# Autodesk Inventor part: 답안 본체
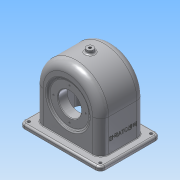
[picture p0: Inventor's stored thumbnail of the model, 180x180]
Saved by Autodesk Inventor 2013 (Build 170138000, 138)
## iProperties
Created: 2016-01
Part Number: 답안 본체
Material: 알루미늄 6061
Document SubType Name: Modeling
Designer: Administrator
Density: 2.71 g/cm^3
Mass: 809.783 g
Surface Area: 999.26 cm^2
Volume: 298.813 cm^3
Author: Administrator
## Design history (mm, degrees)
sketch "스케치1"
  geometry: L1 (-62, 52)-(62, 52); L2 (70, 44)-(70, -44); L3 (62, -52)-(-62, -52); L4 (-70, -44)-(-70, 44); A1 r 8 centre (-62, 44) between (-62, 52) and (-70, 44); A2 r 8 centre (-62, -44) between (-70, -44) and (-62, -52); A3 r 8 centre (62, -44) between (62, -52) and (70, -44); A4 r 8 centre (62, 44) between (70, 44) and (62, 52); 6 further points
  constraints: 8 end point, 8 point on circle, 8 tangent, 6 point on line, 4 centre point, 3 equal radius, 2 midpoint, 2 parallel, 1 horizontal, 1 horizontal alignment, 1 perpendicular, 1 vertical alignment
  dimensions: "d0" = 140 distance of point (-70, 52) point (70, 52); "d2" = 104 distance of point (70, 52) point (70, -52); "d3" = 8 radius of A1
extrude "돌출1" new body sketch "스케치1" distance "d4" = 7; taper "d5" = 0 deg
sketch "스케치2"
  geometry: L1 (62, 7)-(-62, 7) reference; L2 (-57, 7)-(-57, 64); L3 (57, 7)-(57, 64); L4 (-70, 0)-(-70, 7) reference; L5 (-62, 0)-(62, 0) reference; A1 r 57 centre (0, 64) between (57, 64) and (-57, 64); 2 further points
  constraints: 4 end point, 3 point on circle, 2 point on line, 1 centre point, 1 horizontal alignment, 1 parallel, 1 perpendicular, 1 tangent, 1 vertical alignment
  dimensions: "d10" = 57 radius of A1; "d11" = 64 distance from line of L5 L2.end
extrude "돌출2" join sketch "스케치2" stored distance "d12" = 77; taper "d13" = 0 deg
sketch "스케치3"
  geometry: L1 (62, 0)-(-62, 0) reference; C1 r 31 at (0, -60); 1 further point
  constraints: 1 centre point, 1 vertical alignment
  dimensions: "d14" = 62 diameter of C1; "d16" = 60 distance from line of L1 C1.centre
extrude "돌출3" join sketch "스케치3" distance "d17" = 10; taper "d18" = 0 deg
node "작업 평면2"
  node "작업 평면1"
sketch "스케치5"
  geometry: C1 r 6 at (0, 0); 1 further point
  constraints: 1 centre point, 1 coincident
  dimensions: "d20" = 12 diameter of C1
extrude "돌출4" join sketch "스케치5" stored distance "d22" = 5; taper "d23" = 0 deg
sketch "스케치6"
  geometry: L1 (-60.75, 28.203)-(-60.75, 48.797); L2 (-60.75, 48.797)-(14.75, 48.797); L3 (14.75, 48.797)-(14.75, 28.203); L4 (14.75, 28.203)-(-60.75, 28.203); L5 (7, 82.5)-(7, -5.5) reference; 5 further points
  constraints: 3 midpoint, 2 horizontal alignment, 1 parallel, 1 vertical alignment, 2 other
  dimensions: "d24" = 30 distance from line of L5 point (-23, 38.5); "d25" = 7.74973 distance between parallel lines of L3 L5; "d26" = 20.59353 distance between parallel lines of L4 L2
feature "엠보싱1" sketch "스케치6" dims "d0" = 140, "d2" = 104, "d3" = 8, "d27" = 0.5, "d28" = 0
sketch "스케치8"
  geometry: L1 (-57, 7)-(-57, 64) reference; L2 (57, 64)-(57, 7) reference; L3 (-51, 0)-(-51, 64); L4 (51, 64)-(51, 0); L5 (-62, 0)-(62, 0) reference; L6 (-51, 0)-(51, 0); A1 r 57 centre (0, 64) between (57, 64) and (-57, 64) reference; A2 r 51 centre (0, 64) between (51, 64) and (-51, 64); 1 further point
  constraints: 6 end point, 2 horizontal alignment, 2 point on circle, 2 point on line, 2 tangent, 1 centre point
  dimensions: "d30" = 6 radial gap between concentric circles of A1 A2
extrude "돌출5" cut sketch "스케치8" stored distance "d31" = 67; taper "d32" = 0 deg
node "작업 평면3"
sketch "스케치9"
  geometry: C1 r 28 at (0, 60); 1 further point
  constraints: 1 centre point, 1 vertical alignment
  dimensions: "d34" = 56 diameter of C1; "d36" = 60 distance of point (0, 0) C1.centre
extrude "돌출6" join sketch "스케치9" distance "d37" = 16; taper "d38" = 40 deg
hole "구멍1" diameter "d41" = 40; stored, may be unused: countersink angle "d45" = 90 deg, drill point angle "d47" = 0 deg; dims "d42" = 6, "d43" = 4, "d44" = 2, "d46" = 20, "d48" = 10, "d49" = 10
sketch "스케치11"
  geometry: C1 r 31 at (0, 0) reference; A1 r 24 centre (0, 0) between (0, 24) and (-24, 0); 3 further points
  constraints: 4 point on circle, 2 horizontal alignment, 2 vertical alignment, 1 centre point, 1 coincident
  dimensions: "d50" = 48 diameter of A1
hole "구멍2" sketch "스케치11" at (0, 24), (-24, 0), (24, 0), (0, -24) diameter "d52" = 2.459; stored, may be unused: countersink angle "d56" = 90 deg, drill point angle "d58" = 118 deg; dims "d53" = 6, "d54" = 4, "d55" = 2, "d57" = 8
sketch "스케치12"
  geometry: L1 (-19.5, 88)-(-33.5, 99.747) reference; L2 (-19.5, 32)-(-19.5, 88) reference; L3 (-35.5, 60)-(-38.5, 60); L4 (-38.5, 97.416)-(-35.5, 94.899); L5 (-38.5, 121)-(-38.5, 64) reference; L6 (-38.5, 97.416)-(-38.5, 60); L7 (-35.5, 94.899)-(-35.5, 60); 3 further points
  constraints: 8 end point, 3 perpendicular, 2 midpoint, 1 horizontal alignment, 1 point on line
  dimensions: "d59" = 5 distance between parallel lines of L1 L4; "d60" = 3 distance between parallel lines of L7 L6
revolve "회전1" sketch "스케치12" stored, may be unused: angle "d61" = 90 deg
sketch "스케치13"
  geometry: A1 r 28 centre (0, 0) between (0, 28) and (-28, 0); 3 further points
  constraints: 4 point on circle, 3 vertical alignment, 2 horizontal alignment, 1 centre point
  dimensions: "d62" = 56 diameter of A1; "d64" = 60 distance of point (0, -60) A1.centre
hole "구멍3" sketch "스케치13" at (0, 28), (-28, 0), (28, 0), (0, -28) diameter "d65" = 2.459; stored, may be unused: countersink angle "d69" = 90 deg, drill point angle "d71" = 118 deg; dims "d66" = 7, "d67" = 4, "d68" = 2, "d70" = 9
hole "구멍4" diameter "d74" = 40; stored, may be unused: countersink angle "d78" = 90 deg, drill point angle "d80" = 0 deg; dims "d72" = 10, "d73" = 10, "d75" = 7, "d76" = 4, "d77" = 2, "d79" = 16
sketch "스케치14"
  geometry: 5 further points
  constraints: 2 horizontal alignment, 2 vertical alignment
  dimensions: "d81" = 62 horizontal distance of point (0, 0) point (-62, 44); "d82" = 62 horizontal distance of point (62, 44) point (0, 0); "d83" = 44 vertical distance of point (0, 0) point (-62, 44); "d84" = 44 vertical distance of point (-62, -44) point (0, 0)
hole "구멍5" sketch "스케치14" at (-62, 44), (-62, -44), (62, 44), (62, -44) diameter "d85" = 5; stored, may be unused: countersink angle "d89" = 90 deg, drill point angle "d91" = 0 deg; dims "d86" = 7, "d87" = 4, "d88" = 2, "d90" = 7
hole "구멍6" diameter "d94" = 4.459; stored, may be unused: countersink angle "d98" = 90 deg, drill point angle "d100" = 0 deg; dims "d95" = 19, "d96" = 4, "d97" = 2, "d99" = 20, "d111" = 10, "d112" = 10
fillet "모깎기2" dims "d103" = 14
fillet "모깎기3" dims "d104" = 9
fillet "모깎기4" dims "d105" = 1
fillet "모깎기5" dims "d106" = 3
fillet "모깎기6" dims "d107" = 3
chamfer "모따기1" distance "d108" = 1; stored, may be unused: second distance "d109" = 2, angle "d110" = 45 deg
node "솔리드1"
other parameters: "d19" = 6, "d33" = -19
